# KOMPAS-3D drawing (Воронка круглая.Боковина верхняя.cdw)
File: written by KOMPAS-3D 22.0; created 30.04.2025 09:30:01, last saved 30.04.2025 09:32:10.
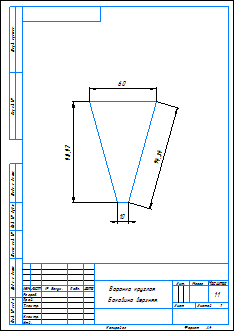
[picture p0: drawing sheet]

Sheet 1: A4, portrait

Document properties: Автор: Admin; Наименование: Воронка круглая Боковина верхняя; Полное имя файла: D:\28.11.2016\3D модели\Абилимпикс\2025\Воронка круглая\Воронка круглая Боковина верхняя..cdw

Title block, sheet 1: Наименование: Воронка круглая / Боковина верхняя.; scale: 1:1; Количество листов документа: 1; Форматы листов документа: A4

Dimensions and other numbers on the sheet: 60; 90,97; 10; 94,34; 1:1; 1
